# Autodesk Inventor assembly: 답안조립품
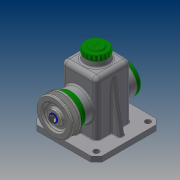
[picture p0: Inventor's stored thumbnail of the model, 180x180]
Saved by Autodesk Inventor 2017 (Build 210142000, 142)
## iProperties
Part Number: 답안조립품
Material: 일반
Document SubType Name: Assembly
Designer: 20
Author: 20
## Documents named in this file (14)
- C:\Users\20\Desktop\470818V1011\답안조립품.iam
- C:\Users\20\Desktop\470818V1011\본체.ipt
- C:\Users\20\Desktop\470818V1011\앞커버.ipt
- C:\Users\20\Desktop\470818V1011\뒤커버.ipt
- C:\Users\20\Desktop\470818V1011\상부캡.ipt
- C:\Users\20\Desktop\470818V1011\베어링 15 x 35 x 11.ipt
- C:\Users\20\Desktop\470818V1011\오일실 15 25 7.ipt
- C:\Users\20\Desktop\470818V1011\축.ipt
- C:\Users\20\Desktop\470818V1011\멈춤링 15 x 1.ipt
- C:\Users\20\Desktop\470818V1011\키 5 x 5 x 14.ipt
- C:\Users\20\Desktop\470818V1011\V-벨트풀리.ipt
- C:\Users\20\Desktop\470818V1011\볼트 M6 x 12.ipt
- C:\Users\20\Desktop\470818V1011\와셔.ipt
- C:\Users\20\Desktop\470818V1011\볼트 M4 x 10.ipt
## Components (1 placed, 1 different names)
1. V-벨트풀리:1
